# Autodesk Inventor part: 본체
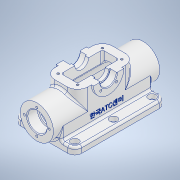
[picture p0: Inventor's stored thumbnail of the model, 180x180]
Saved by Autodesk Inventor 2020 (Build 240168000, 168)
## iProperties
Created: 2024-06
Part Number: 본체
Material: 알루미늄 6061
Document SubType Name: Modeling
Designer: oem
Mass: 550.805 g
Surface Area: 613.924 cm^2
Volume: 204.002 cm^3
Density: 2.7 g/cm^3
Appearance: 알루미늄 - 평지
Author: oem
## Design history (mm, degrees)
sketch "스케치1"
  geometry: C1 r 24 at (0, 0); 1 further point
  constraints: 1 centre point, 1 coincident
  dimensions: "d0" = 48 diameter of C1
extrude "돌출1" new body sketch "스케치1" stored distance "d1" = 154; taper "d2" = 0 deg
node "작업 평면1"
sketch "스케치2"
  geometry: L1 (-24, -77)-(-24, 77) reference; L2 (24, 42)-(-24, 42); L3 (-24, 42)-(-24, -42); L4 (-24, -42)-(24, -42); L5 (24, -42)-(24, 42); L6 (24, 42)-(-24, -42); L7 (-24, 42)-(24, -42); 2 further points
  constraints: 12 end point, 2 midpoint, 2 parallel, 1 horizontal, 1 perpendicular, 1 point on line
  dimensions: "d4" = 84 distance of L3.end L2.end
extrude "돌출2" join sketch "스케치2" stored distance "d5" = 154; taper "d6" = 0 deg
fillet "모깎기1" dims "d8" = 15
sketch "스케치3"
  geometry: L1 (-24, 0)-(-24, -18); L2 (-24, -18)-(-44, -18); L3 (-44, -18)-(-44, -28); L4 (-44, -28)-(44, -28); L5 (44, -28)-(44, -18); L6 (44, -18)-(24, -18); L7 (24, -18)-(24, 0); A1 r 24 centre (0, 0) between (-24, 0) and (24, 0) reference; 2 further points
  constraints: 14 end point, 4 perpendicular, 2 point on circle, 2 point on line, 2 tangent, 1 midpoint, 1 parallel, 1 vertical, 1 vertical alignment
  dimensions: "d9" = 10 distance of L2.end L3.end; "d10" = 88 distance of L3.end L4.end; "d11" = 28 distance of point (0, 0) point (0, -28)
extrude "돌출3" join sketch "스케치3" stored distance "d12" = 132; taper "d13" = 0 deg
sketch "스케치4"
  geometry: C1 r 24 at (0, 0) reference; C2 r 14 at (0, 0)
  constraints: 1 centre point, 1 coincident
  dimensions: "d14" = 28 diameter of C2
extrude "돌출4" cut sketch "스케치4" distance "d15" = 15; taper "d16" = 0 deg
sketch "스케치5"
  geometry: C1 r 24 at (0, 0) reference; C2 r 14 at (0, 0)
  constraints: 1 centre point, 1 coincident
  dimensions: "d17" = 28 diameter of C2
extrude "돌출5" cut sketch "스케치5" distance "d18" = 15; taper "d19" = 0 deg
sketch "스케치6"
  geometry: C1 r 14 at (0, 0) reference; C2 r 11 at (0, 0)
  constraints: 1 centre point, 1 coincident
  dimensions: "d21" = 22 diameter of C2
extrude "돌출6" cut sketch "스케치6" extent not by distance; stored distance "d22" = 15; taper "d23" = 0 deg
sketch "스케치7"
  geometry: L1 (-12, -30)-(12, -30); L2 (12, -30)-(12, 30); L3 (12, 30)-(-12, 30); L4 (-12, 30)-(-12, -30); L5 (-12, -30)-(12, 30); L6 (12, -30)-(-12, 30); 1 further point
  constraints: 12 end point, 2 midpoint, 2 parallel, 1 horizontal, 1 perpendicular
  dimensions: "d24" = 24 distance of L3.end L2.end; "d25" = 60 distance of L2.end L1.end
extrude "돌출7" cut sketch "스케치7" extent not by distance; stored distance "d26" = 0; taper "d27" = 0 deg
fillet "모깎기2" dims "d28" = 3
sketch "스케치8"
  geometry: L1 (-14, 32)-(14, 32); L2 (-14, -32)-(-14, 32); 4 further points
  constraints: 4 end point, 3 horizontal alignment, 3 vertical alignment, 2 midpoint, 1 horizontal, 1 perpendicular
  dimensions: "d29" = 64 distance of L1.start L2.start; "d30" = 28 distance of L1.end L1.start
hole "구멍1" sketch "스케치8" at (-14, 32), (14, 32), (14, -32), (-14, -32) diameter "d31" = 3.242; stored, may be unused: countersink angle "d35" = 90 deg, drill point angle "d37" = 118 deg; dims "d32" = 8, "d33" = 8, "d34" = 2, "d36" = 10
sketch "스케치9"
  geometry: L1 (0, 0)-(54, 0) reference; L2 (0, 0)-(54, 0) reference; A1 r 22 centre (27, 0) between (5, 0) and (49, 0); 3 further points
  constraints: 2 point on circle, 2 point on line, 1 centre point, 1 midpoint
  dimensions: "d38" = 44 diameter of A1
extrude "돌출8" join sketch "스케치9" distance "d39" = 3; taper "d40" = 0 deg
sketch "스케치10"
  geometry: L1 (49, 0)-(5, 0) reference; A1 r 22 centre (27, 0) between (5, 0) and (49, 0) reference; A2 r 12 centre (27, 0) between (15, 0) and (39, 0); 1 further point
  constraints: 2 point on circle, 2 point on line, 1 centre point, 1 coincident
  dimensions: "d41" = 24 diameter of A2
extrude "돌출9" cut sketch "스케치10" distance "d42" = 10; taper "d43" = 0 deg
sketch "스케치11"
  geometry: L1 (0, 0)-(54, 0) reference; L2 (39, 0)-(15, 0) reference; A1 r 22 centre (27, 0) between (5, 0) and (49, 0); 1 further point
  constraints: 2 point on circle, 2 point on line, 1 centre point, 1 midpoint
  dimensions: "d44" = 44 diameter of A1
extrude "돌출10" join sketch "스케치11" distance "d45" = 3; taper "d46" = 0 deg
sketch "스케치12"
  geometry: L1 (49, 0)-(5, 0) reference; A1 r 22 centre (27, 0) between (5, 0) and (49, 0) reference; A2 r 12 centre (27, 0) between (15, 0) and (39, 0); 1 further point
  constraints: 2 point on circle, 2 point on line, 1 centre point, 1 coincident
  dimensions: "d47" = 24 diameter of A2
extrude "돌출11" cut sketch "스케치12" distance "d48" = 10; taper "d49" = 0 deg
sketch "스케치13"
  geometry: L1 (15, 0)-(39, 0) reference; A1 r 12 centre (27, 0) between (15, 0) and (39, 0) reference; A2 r 10 centre (27, 0) between (17, 0) and (37, 0); 1 further point
  constraints: 2 point on circle, 2 point on line, 1 centre point, 1 coincident
  dimensions: "d50" = 20 diameter of A2
extrude "돌출12" cut sketch "스케치13" extent not by distance; stored distance "d51" = 10; taper "d52" = 0 deg
sketch "스케치14"
  geometry: L1 (44, -28)-(-44, -28) reference; L2 (-18, -28)-(-18, 0); L3 (18, -28)-(18, 0); A1 r 18 centre (0, 0) between (18, 0) and (-18, 0); 2 further points
  constraints: 4 end point, 3 point on circle, 2 point on line, 2 tangent, 2 vertical, 1 centre point, 1 vertical alignment
  dimensions: "d53" = 18 radius of A1; "d54" = 28 distance of L3.start L3.end
extrude "돌출13" cut sketch "스케치14" stored distance "d55" = 120; taper "d56" = 0 deg
sketch "스케치15"
  geometry: C1 r 14 at (0, 0) reference; 1 further point
  constraints: 1 vertical alignment
  dimensions: "d57" = 18 distance of C1.centre point (0, 18)
hole "구멍2" sketch "스케치15" at (0, 18) diameter "d58" = 3.242; stored, may be unused: countersink angle "d62" = 90 deg, drill point angle "d64" = 118 deg; dims "d59" = 8, "d60" = 8, "d61" = 2, "d63" = 10
sketch "스케치16"
  geometry: L1 (20, 132)-(20, 0) reference; L2 (-68, 0)-(-68, 132) reference; L3 (-48, 0)-(-68, 0) reference; 7 further points
  constraints: 3 horizontal alignment, 3 vertical alignment
  dimensions: "d69" = 68 distance of point (10, 122) point (-58, 122); "d71" = 10 distance from line of L2 point (-58, 122); "d72" = 10 distance from line of L2 point (-58, 10); "d73" = 10 distance from line of L1 point (10, 122); "d74" = 112 distance of point (-58, 122) point (-58, 10); "d75" = 10 distance from line of point (-58, 10) L3
hole "구멍3" sketch "스케치16" at (10, 122), (10, 66), (10, 10), (-58, 10), (-58, 66), (-58, 122) diameter "d76" = 6.6; stored, may be unused: countersink angle "d80" = 90 deg, drill point angle "d82" = 118 deg; dims "d77" = 8, "d78" = 11, "d79" = 6.6, "d81" = 10
sketch "스케치17"
  geometry: L1 (27, 0)-(15.686, -11.314); L2 (27, 0)-(38.314, -11.314); L3 (27, 0)-(27, -31); A1 r 22 centre (27, 0) between (5, 0) and (49, 0) reference; A2 r 10 centre (27, 0) between (17, 0) and (37, 0) reference
  constraints: 6 end point, 1 perpendicular, 1 vertical
  dimensions: "d84" = 45 deg angle of L3 L1; "d85" = 16 distance of L1.start L1.end; "d86" = 45 deg angle of L3 L2
hole "구멍4" sketch "스케치17" at (15.686, -11.314), (38.314, -11.314) diameter "d87" = 3.242; stored, may be unused: countersink angle "d91" = 90 deg, drill point angle "d93" = 118 deg; dims "d88" = 8, "d89" = 11, "d90" = 6.6, "d92" = 10
sketch "스케치18"
  geometry: L1 (93, -28)-(-39, -28) reference; 2 further points
  constraints: 1 vertical alignment, 1 other
  dimensions: "d94" = 20 distance from line of L1 point (27, -8)
feature "엠보싱1" sketch "스케치18" dims "d95" = 0.5, "d96" = 0
fillet "모깎기3" dims "d97" = 10
fillet "모깎기4" dims "d98" = 3
fillet "모깎기5" dims "d99" = 3
fillet "모깎기6" dims "d100" = 3
chamfer "모따기1" distance "d101" = 1; stored, may be unused: second distance "d102" = 2, angle "d103" = 45 deg
fillet "모깎기7" dims "d104" = 3
fillet "모깎기8" dims "d105" = 3
fillet "모깎기9" dims "d106" = 0.3
fillet "모깎기10" dims "d107" = 3
fillet "모깎기11" dims "d108" = 3
fillet "모깎기12" dims "d109" = 3
node "솔리드1"
pattern_circular "원형 패턴1" dims angle "d66" = 360 deg
mirror "미러1"
mirror "미러2"
feature "A9D066F2-1C7D-4E18-AEED-F7BC21143FA4" dims "d76" = 6.6, "d77" = 8, "d78" = 11, "d79" = 6.6, "d80" = 90 deg, "d81" = 10, "d82" = 118 deg
other parameters: "d3" = 31
